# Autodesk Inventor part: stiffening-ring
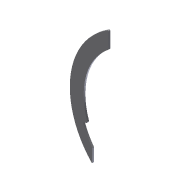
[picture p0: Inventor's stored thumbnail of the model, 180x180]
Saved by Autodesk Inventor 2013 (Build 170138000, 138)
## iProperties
Created: 2012-05
Part Number: stiffening-ring
Document SubType Name: Modeling
Designer: yh63
Density: 1 g/cm^3
Material: Generic
d0: 4.000 in
d1: 38.125 in
d2: 0.500 in
d3: 0.00 deg
d7: 0.00 deg
d8: 90.00 deg
d9: 90.00 deg
d10: 23.800 in
d11: 11.900 in
d12: 8.000 in
d14: 0.00 deg
d15: 16.550 in
d16: 16.000 in
d17: 1.000 in
d18: 0.00 deg
d23: 20.500 in
d27: 20.00 deg
d29: 1.000 in
d30: 0.00 deg
Author: yh63
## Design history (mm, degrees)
sketch "Sketch1"
  geometry: C1 r 484.188 at (0, 0); C2 r 585.788 at (0, 0); 1 further point
  constraints: 2 centre point, 2 coincident
  dimensions: "d0" = 101.6 radial gap between concentric circles of C2 C1; "d1" = 968.375 diameter of C1
extrude "Extrusion1" new body sketch "Sketch1" distance "d2" = 12.7; taper "d3" = 0 deg
sketch "Sketch2"
  geometry: L1 (-585.788, 12.7)-(585.788, 12.7) reference; L2 (-585.788, 0)-(585.788, 0) reference; L3 (-585.788, 0)-(-585.788, 12.7) reference; L4 (0, -2.54)-(0, 15.24) reference; L5 (-302.26, 12.7)-(-302.26, 0); L6 (302.26, 0)-(302.26, 12.7); L7 (302.26, 0)-(-302.26, 0); L8 (-302.26, 12.7)-(302.26, 12.7); 1 further point
  constraints: 8 end point, 4 point on line, 2 collinear
  dimensions: "d8" = 90 deg angle of L2 L5; "d9" = 90 deg angle of L2 L6; "d10" = 604.52 distance of L6.start L5.end; "d11" = 302.26 distance from line of L4 L5.end
extrude "Extrusion2" cut sketch "Sketch2" stored distance "d6" = 152.4; taper "d7" = 0 deg
sketch "Sketch3"
  geometry: L1 (-420.37, -203.2)-(420.37, -203.2); L2 (420.37, -203.2)-(420.37, -609.6); L3 (420.37, -609.6)-(-420.37, -609.6); L4 (-420.37, -609.6)-(-420.37, -203.2); A1 r 484.188 centre (0, 0) between (-302.26, 378.254) and (302.26, 378.254) reference
  constraints: 8 end point, 2 parallel, 1 horizontal, 1 perpendicular
  dimensions: "d12" = 203.2 distance from line of L1 A1.centre; "d15" = 420.37 distance from line of A1.centre L4; "d16" = 406.4 distance of L3.end L1.start; "d34" = 840.74 distance between parallel lines of L2 L4
extrude "Extrusion3" cut sketch "Sketch3" stored distance "d13" = 0; taper "d14" = 0 deg
sketch "Sketch4"
  geometry: L1 (0, 552.073)-(754.525, 552.073); L2 (754.525, 552.073)-(754.525, -489.814); L3 (754.525, -489.814)-(0, -489.814); L4 (0, -489.814)-(0, 552.073)
  constraints: 8 end point, 2 parallel, 1 horizontal, 1 perpendicular
extrude "Extrusion4" cut sketch "Sketch4" distance "d17" = 25.4; taper "d18" = 0 deg
sketch "Sketch5"
  geometry: L1 (0, 0)-(-489.318, -178.097); L2 (0, 0)-(-398.879, -334.7); A1 r 520.7 centre (0, 0) between (-489.298, -178.09) and (-398.879, -334.7)
  constraints: 4 end point, 2 point on circle, 1 centre point, 1 point on line
  dimensions: "d23" = 520.7 radius of A1; "d27" = 20 deg angle of L2 L1
extrude "Extrusion5" cut sketch "Sketch5" distance "d29" = 25.4; taper "d30" = 0 deg
chamfer "Chamfer1" distance "d31" = 6.35; stored, may be unused: second distance "d32" = 3.175, angle "d33" = 45 deg
body "Solid1"
